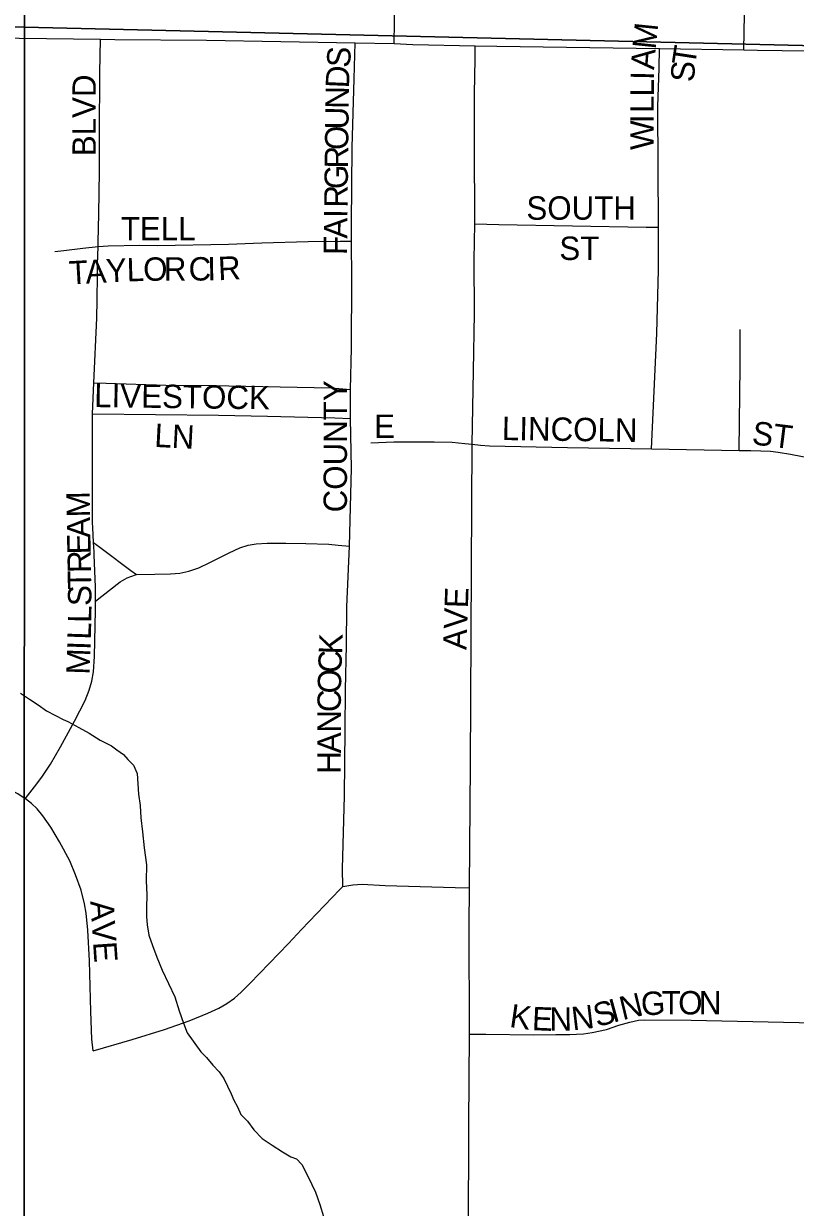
# Model space of a CAD drawing. Extents: x 1587405 to 1714697, y 1028970 to 1155083.
# Drawn here: x 1656161 to 1657810, y 1105700 to 1108229 of the extents above; entities that cross this region are included whole.
import ezdxf

# ---------------------------------------------------------------- set-up
doc = ezdxf.new("R2010")
doc.units = 0
for name, color, linetype in [('GM_X_City_Street', 7, 'Continuous'), ('GM_X_City_Street_Text', 7, 'Continuous'), ('GM_X_Minor_River', 7, 'Continuous'), ('GM_X_Section', 7, 'Continuous'), ('GM_X_State_Route', 7, 'Continuous')]:
    doc.layers.add(name, color=color, linetype=linetype)

msp = doc.modelspace()

# ---------------------------------------------------------------- linework, layer by layer
at = {"layer": 'GM_X_City_Street'}
for points in [[(1657699.9, 1108173.4), (1657710.5, 1108700), (1657723.2, 1109737.5)], [(1656953.2, 1108186.9), (1656953.6, 1108232.4), (1656954.9, 1108396.6), (1656955.4, 1108478.7), (1656956.2, 1108495.4), (1656958, 1108510.8), (1656960.1, 1108528.4), (1656962.2, 1108546.1)], [(1656320.2, 1107752.8), (1656320.5, 1107763.3), (1656321.9, 1107822.3), (1656323.1, 1107914.3), (1656323.3, 1108025.9), (1656324.2, 1108091.5), (1656323.8, 1108124.5), (1656325.2, 1108195.9)], [(1656862, 1107764.6), (1656861.8, 1107801.2), (1656863.2, 1107964.7), (1656867.3, 1108111.2), (1656869.5, 1108188.3)], [(1657124.9, 1107921.1), (1657124.9, 1108079.4), (1657125.8, 1108154.4), (1657126.1, 1108182)], [(1657517.6, 1107794.2), (1657516.5, 1108052.3), (1657519, 1108133.9), (1657520.3, 1108176)], [(1657125.1, 1107801.2), (1657125, 1107855.3), (1657124.9, 1107921.1)], [(1657119.8, 1107330.4), (1657122.2, 1107487.2), (1657124.3, 1107610.2), (1657123.6, 1107724.7), (1657125.1, 1107801.2)], [(1657125.1, 1107801.2), (1657176.5, 1107800.2), (1657491.4, 1107794.7), (1657517.6, 1107794.2)], [(1657503.1, 1107320.9), (1657514.2, 1107567.2), (1657517.9, 1107703.2), (1657517.9, 1107744.6), (1657517.6, 1107794.2)], [(1656228, 1107742.6), (1656247.2, 1107744.4), (1656287.9, 1107749.2), (1656320.2, 1107752.8)], [(1656311, 1107461.8), (1656317.2, 1107600.2), (1656318, 1107639.4), (1656318.9, 1107691.6), (1656319.2, 1107714.4), (1656320.2, 1107752.8)], [(1656320.2, 1107752.8), (1656342.1, 1107754.3), (1656409.3, 1107755.9), (1656447, 1107755.5), (1656598.6, 1107758.4), (1656670, 1107760.7), (1656769.1, 1107763.5), (1656837.4, 1107764.4), (1656862, 1107764.6)], [(1656859.5, 1107447.8), (1656862, 1107535.7), (1656862.4, 1107683.3), (1656862, 1107764.6)], [(1657690.1, 1107317.2), (1657692.4, 1107497.4), (1657692.4, 1107575.4)], [(1656308, 1107395.7), (1656311, 1107461.8)], [(1656311, 1107461.8), (1656337.7, 1107460.9), (1656465.3, 1107457), (1656563.4, 1107456.2), (1656818.5, 1107450.8), (1656859.5, 1107447.8)], [(1656859.4, 1107385.7), (1656859.5, 1107447.8)], [(1656308, 1107395.7), (1656577.4, 1107392.3), (1656682.1, 1107390.6), (1656826.1, 1107387), (1656859.4, 1107385.7)], [(1656310.5, 1107120.6), (1656308.8, 1107152.9), (1656308.4, 1107162.7), (1656308, 1107395.7)], [(1656857.4, 1107112.6), (1656861.5, 1107279.6), (1656859.4, 1107385.7)], [(1656902.8, 1107333.3), (1656952.6, 1107335.4), (1657038.3, 1107335.6), (1657077, 1107334.9), (1657103.7, 1107332.4), (1657119.8, 1107330.4)], [(1657113.9, 1106382.3), (1657115.9, 1106645.5), (1657119.1, 1107201.6), (1657119.8, 1107330.4)], [(1657119.8, 1107330.4), (1657137.4, 1107328.2), (1657157, 1107326.9), (1657323.2, 1107323.5), (1657503.1, 1107320.9)], [(1657503.1, 1107320.9), (1657690.1, 1107317.2)], [(1657690.1, 1107317.2), (1657715.3, 1107316.8), (1657736.5, 1107316.5), (1657757, 1107315.4), (1657773.7, 1107313.2), (1657799.6, 1107309.2), (1657876.6, 1107294.3), (1657893.4, 1107291.4), (1657912.1, 1107288.9), (1657927.6, 1107287.2), (1657941.5, 1107286.5), (1657990.5, 1107286), (1658030.1, 1107285.7)], [(1656314.8, 1106995.2), (1656314.6, 1107025), (1656312, 1107094.1), (1656311.5, 1107100.6), (1656310.5, 1107120.6)], [(1656310.5, 1107120.6), (1656329.9, 1107106.1), (1656390.5, 1107060.8), (1656402.2, 1107052.1)], [(1656402.2, 1107052.1), (1656441.7, 1107052.8), (1656475.3, 1107053.5), (1656494.9, 1107055), (1656514, 1107059), (1656535.5, 1107066.7), (1656559.1, 1107078.1), (1656600, 1107098.6), (1656623.2, 1107109.1), (1656641, 1107115), (1656658.4, 1107117.4), (1656681.9, 1107119.2), (1656721.6, 1107119.3), (1656764.2, 1107118.5), (1656813.6, 1107116.8), (1656833, 1107115.1), (1656857.4, 1107112.6)], [(1656843.3, 1106385.1), (1656842.9, 1106423.3), (1656846.8, 1106579.3), (1656848.5, 1106720.4), (1656849.3, 1106805.8), (1656851.2, 1106901), (1656852, 1106983), (1656857.4, 1107112.6)], [(1656314.8, 1106995.2), (1656328.5, 1107005.9), (1656367.6, 1107036.4), (1656382.2, 1107044.9), (1656390.2, 1107048.1), (1656402.2, 1107052.1)], [(1656164.6, 1106572.9), (1656184, 1106598), (1656200.3, 1106619), (1656218.5, 1106646.6), (1656240.2, 1106683.7), (1656269.7, 1106738.8), (1656292.3, 1106782.9), (1656301.2, 1106804.6), (1656306.8, 1106824), (1656310.2, 1106843.8), (1656312.8, 1106877), (1656314.8, 1106975.6), (1656314.8, 1106995.2)], [(1656164.6, 1106572.9), (1656148.4, 1106583.3), (1656101.8, 1106607.4), (1656018.1, 1106652.8), (1655948.9, 1106690.6), (1655864.3, 1106741), (1655779.2, 1106795.7)], [(1656309.4, 1106034.1), (1656306.7, 1106058.8), (1656304.8, 1106117.9), (1656302.1, 1106226.2), (1656298, 1106291.7), (1656294.8, 1106328.5), (1656291.5, 1106348.3), (1656284.2, 1106377.4), (1656272.3, 1106410.4), (1656259.7, 1106440.1), (1656237.5, 1106480.7), (1656219.3, 1106512), (1656202.5, 1106536.3), (1656189.8, 1106551.3), (1656177.9, 1106562.6), (1656165, 1106572.7), (1656164.6, 1106572.9)], [(1656309.4, 1106034.1), (1656393.3, 1106058.5), (1656462.2, 1106079.9), (1656514.9, 1106098.3), (1656554.5, 1106114.3), (1656578.3, 1106125.3), (1656595.4, 1106135.2), (1656611.4, 1106146.6), (1656626.3, 1106159.4), (1656644.6, 1106178.3), (1656726.9, 1106263.5), (1656754.8, 1106293.4), (1656836.9, 1106379.2), (1656843.3, 1106385.1)], [(1656843.3, 1106385.1), (1656864.8, 1106388.6), (1656884.4, 1106390), (1656933.6, 1106387.6), (1657083.4, 1106383.2), (1657113.9, 1106382.3)], [(1657113.7, 1106069.7), (1657113.3, 1106302.3), (1657113.9, 1106382.3)], [(1657113.7, 1106069.7), (1657148.9, 1106069.6), (1657250.4, 1106068.2), (1657298.2, 1106068.9), (1657328.3, 1106069.3), (1657342.3, 1106069.5), (1657357.6, 1106070.6), (1657375.8, 1106073.2), (1657406.5, 1106079.7), (1657433.3, 1106088.7), (1657456.9, 1106095.7), (1657475.3, 1106099.6), (1657488.1, 1106100.7), (1657587.6, 1106099.6), (1657883.7, 1106093.2)], [(1657109.1, 1105361.2), (1657110.5, 1105566.7), (1657112.4, 1105795.2), (1657112.2, 1105876.6), (1657113.7, 1106069.7)]]:
    msp.add_lwpolyline(points, dxfattribs=at)
at = {"layer": 'GM_X_Minor_River'}
msp.add_lwpolyline([(1656154.2, 1106798.2), (1656174, 1106785.8), (1656191.9, 1106773.3), (1656209.7, 1106760.9), (1656229.5, 1106750.5), (1656245.4, 1106742.2), (1656255.3, 1106738), (1656279.2, 1106725.4), (1656301, 1106713), (1656324.8, 1106698.4), (1656348.6, 1106685.9), (1656360.5, 1106677.7), (1656374.3, 1106667.4), (1656384.1, 1106657.1), (1656395.9, 1106644.9), (1656403.6, 1106626.6), (1656405.2, 1106604.6), (1656406.7, 1106582.4), (1656410.2, 1106558.3), (1656411.7, 1106532.2), (1656415.1, 1106502), (1656418.4, 1106467.9), (1656423.7, 1106431.6), (1656423, 1106397.6), (1656424.4, 1106367.4), (1656423.8, 1106339.4), (1656423.5, 1106321.3), (1656425.1, 1106303.2), (1656428.7, 1106281.1), (1656436.3, 1106258.9), (1656445.8, 1106234.6), (1656457.3, 1106206.3), (1656470.7, 1106177.9), (1656484.2, 1106149.6), (1656493.6, 1106119.3), (1656503.1, 1106093), (1656510.8, 1106072.8), (1656540, 1106032.1), (1656551.8, 1106019.8), (1656565.5, 1106003.5), (1656579.3, 1105989.2), (1656589, 1105974.9), (1656596.7, 1105958.8), (1656604.4, 1105942.5), (1656610.2, 1105928.4), (1656617.9, 1105914.2), (1656625.6, 1105898), (1656639.4, 1105883.7), (1656653, 1105865.3), (1656670.7, 1105846.9), (1656692.5, 1105832.4), (1656714.3, 1105818), (1656732.1, 1105807.6), (1656744.1, 1105803.3), (1656755.9, 1105791.1), (1656769.4, 1105764.7), (1656784.8, 1105732.3), (1656794.3, 1105706), (1656801.8, 1105679.8)], dxfattribs=at)
at = {"layer": 'GM_X_Section'}
for points in [[(1656195.7, 1113439), (1656163.1, 1108222.1), (1651041.3, 1108325.5), (1651152, 1113557.3)], [(1661579.6, 1113384), (1661543.6, 1108095.1), (1656163.1, 1108222.1), (1656195.7, 1113439)], [(1651041.3, 1108325.5), (1656163.1, 1108222.1), (1656161.5, 1102928.9), (1650963.1, 1102991.2), (1650961.9, 1103051.3)], [(1656163.1, 1108222.1), (1661543.6, 1108095.1), (1661485.6, 1102806.5), (1656161.5, 1102928.9)]]:
    msp.add_lwpolyline(points, close=True, dxfattribs=at)
at = {"layer": 'GM_X_State_Route'}
msp.add_lwpolyline([(1656035.7, 1108199.5), (1656325.2, 1108195.9), (1656356, 1108195.6), (1656552, 1108193.7), (1656869.5, 1108188.3), (1656953.2, 1108186.9), (1656992.7, 1108184.8), (1657126.1, 1108182), (1657172.6, 1108181), (1657520.3, 1108176), (1657699.9, 1108173.4), (1657729.2, 1108173), (1658096.3, 1108167.5), (1658171.1, 1108166.4), (1658334.8, 1108163.8), (1658629.3, 1108158.4), (1659028.2, 1108148.9), (1659349.6, 1108141.1), (1659608.8, 1108137.4), (1659742.5, 1108137.3), (1660013.6, 1108132.7)], dxfattribs=at)

# ---------------------------------------------------------------- texts
at = {"layer": 'GM_X_City_Street_Text'}
for s, rotation, p in [('M', 84.1245, (1657511.7, 1108173.4)), ('S', 86.0351, (1656858.1, 1108134.3)), ('T', 81.2788, (1657595.7, 1108137.6)), ('A', 85.5594, (1657508.3, 1108129.8)), ('D', 87.7041, (1656856.3, 1108090.7)), ('S', 86.6095, (1657593.8, 1108103.7)), ('BLVD', 90, (1656315.4, 1107946.1)), ('L', 89.9572, (1657507.9, 1108073.7)), ('I', 88.7755, (1657507.9, 1108108.6)), ('N', 89.317, (1656855.8, 1108047.1)), ('L', 89.9453, (1657507.8, 1108038.5)), ('U', 89.317, (1656855.3, 1108003.1)), ('I', 89.9573, (1657507.8, 1108016.5)), ('O', 89.317, (1656854.8, 1107959.1)), ('W', 89.9496, (1657507.8, 1107959.3)), ('R', 89.32, (1656854.3, 1107919.5)), ('G', 89.317, (1656853.8, 1107875.5)), ('R', 89.32, (1656853.3, 1107835.9)), ('SOUTH', 0, (1657235.6, 1107810.3)), ('I', 89.315, (1656853.1, 1107813.9)), ('TELL', 0, (1656368.8, 1107766.3)), ('A', 89.317, (1656852.6, 1107769.9)), ('F', 89.317, (1656852.1, 1107734.7)), ('ST', 0, (1657306, 1107724.3)), ('T', 3.2526, (1656259.3, 1107671.6)), ('A', 3.215, (1656294.5, 1107673.6)), ('Y', 2.8209, (1656338.3, 1107676.1)), ('L', 1.7763, (1656382, 1107678.3)), ('O', 1.0929, (1656417, 1107679.4)), ('R', 0.1214, (1656460.8, 1107680.2)), ('C', 0.1128, (1656513.7, 1107680.3)), ('I', 0.9397, (1656554, 1107680.4)), ('R', 2.8197, (1656577.8, 1107680.8)), ('LIVESTOCK', 359.2563, (1656311.7, 1107409.9)), ('COUNTY', 90, (1656852.1, 1107184.9)), ('E', 0, (1656910, 1107343.9)), ('LN', 356.989, (1656439.6, 1107324.9)), ('LINCOLN', 359.1935, (1657182.9, 1107339.5)), ('ST', 352.8683, (1657716, 1107330.7)), ('M', 90.972, (1656303.2, 1107174.6)), ('A', 90.9399, (1656303.9, 1107130.6)), ('E', 90.9562, (1656304.5, 1107095.4)), ('R', 90.9795, (1656305.2, 1107055.8)), ('T', 90.9497, (1656305.8, 1107020.6)), ('S', 90.6733, (1656306.2, 1106985.1)), ('AVE', 88.0264, (1657107.4, 1106890.4)), ('L', 89.1412, (1656305.7, 1106948.5)), ('L', 88.1691, (1656304.5, 1106912.3)), ('K', 87.9452, (1656841.6, 1106880.8)), ('M', 88.1782, (1656302.2, 1106837.6)), ('I', 88.1863, (1656303.9, 1106890.4)), ('C', 87.984, (1656840.2, 1106841.2)), ('O', 88.5357, (1656839.1, 1106797.3)), ('C', 89.83, (1656839, 1106758)), ('N', 89.9781, (1656839, 1106714.1)), ('A', 89.9928, (1656839, 1106670.1)), ('H', 89.9781, (1656838.9, 1106626.1)), ('A', 273.9159, (1656303.4, 1106354)), ('V', 273.9159, (1656306.4, 1106310.1)), ('E', 273.8832, (1656309.4, 1106266.2)), ('N', 13.5221, (1657441.2, 1106099.5)), ('G', 3.1932, (1657481.7, 1106109.4)), ('T', 0.082, (1657524.9, 1106111.8)), ('O', 0, (1657560, 1106111.9)), ('N', 0, (1657604, 1106111.9)), ('K', 351.7308, (1657197.8, 1106085.3)), ('E', 357.4412, (1657246.7, 1106078.5)), ('N', 6.7439, (1657334.8, 1106077.7)), ('S', 15.3447, (1657386.5, 1106084.5)), ('I', 15.2666, (1657420.4, 1106093.8)), ('N', 0.6462, (1657285, 1106076.9))]:
    msp.add_text(s, height=50, rotation=rotation, dxfattribs=at).set_placement(p)

doc.saveas('drawing.dxf')
